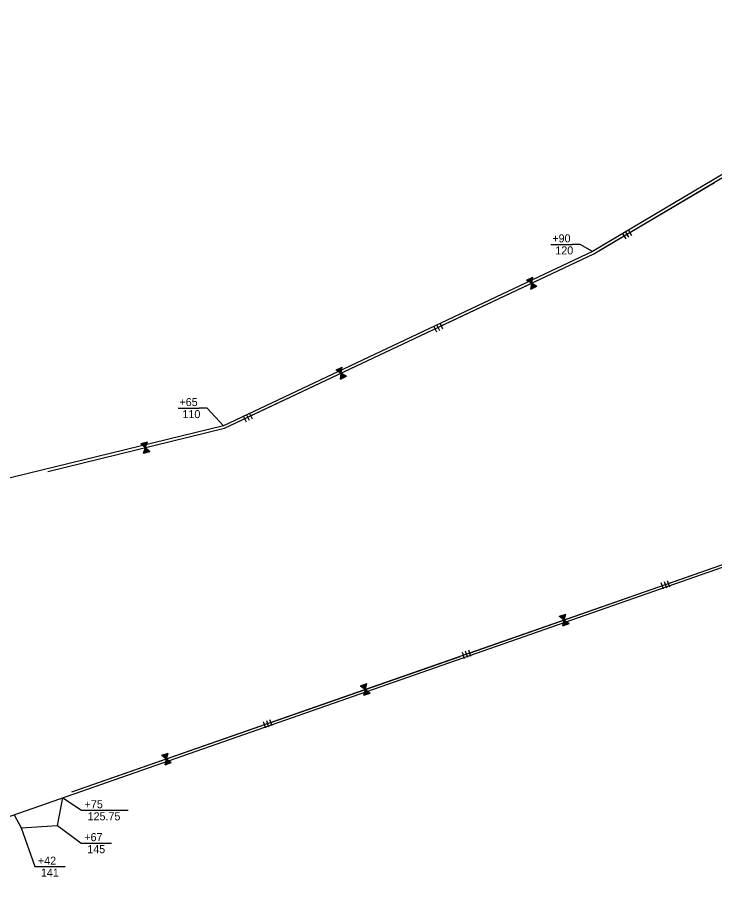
# Model space of a CAD drawing. Extents: x 979729 to 993523, y 1834148 to 1845433.
# Drawn here: x 990066 to 990587, y 1838700 to 1839360 of the extents above; entities that cross this region are included whole.
import ezdxf

# ---------------------------------------------------------------- set-up
doc = ezdxf.new("R2010")
doc.units = 0
for name, color, linetype in [('42', 7, 'Continuous'), ('51', 7, 'Continuous'), ('53', 7, 'Continuous'), ('R_Draft', 7, 'Continuous')]:
    doc.layers.add(name, color=color, linetype=linetype)

msp = doc.modelspace()

# ---------------------------------------------------------------- linework, layer by layer
at = {"layer": '42'}
for p, q in [((990496.48, 1839183.82), (990791.28, 1839358.59)), ((990522.05, 1839201.89), (990524.6, 1839197.59)), ((990517.75, 1839199.34), (990520.3, 1839195.04)), ((990519.9, 1839200.62), (990522.45, 1839196.32)), ((990220.2, 1839053.4), (990496.48, 1839183.82)), ((990446.24, 1839164.25), (990450.1, 1839161.93)), ((990446.31, 1839164.23), (990446.32, 1839164.29)), ((990446.55, 1839164.11), (990446.59, 1839164.42)), ((990446.78, 1839163.95), (990446.87, 1839164.55)), ((990447.01, 1839163.83), (990447.14, 1839164.68)), ((990447.24, 1839163.67), (990447.41, 1839164.81)), ((990447.47, 1839163.51), (990447.68, 1839164.94)), ((990447.71, 1839163.39), (990447.95, 1839165.06)), ((990447.95, 1839163.34), (990448.2, 1839165.03)), ((990448.17, 1839163.14), (990448.5, 1839165.32)), ((990448.41, 1839163.02), (990448.77, 1839165.45)), ((990448.63, 1839162.83), (990449.04, 1839165.58)), ((990448.87, 1839162.74), (990449.31, 1839165.7)), ((990449.1, 1839162.56), (990449.58, 1839165.83)), ((990449.33, 1839162.44), (990449.85, 1839165.96)), ((990449.56, 1839162.28), (990450.13, 1839166.09)), ((990449.8, 1839162.18), (990450.4, 1839166.22)), ((990450.03, 1839162), (990450.67, 1839166.35)), ((990450.1, 1839161.93), (990450.76, 1839166.39)), ((990449.44, 1839157.47), (990450.1, 1839161.93)), ((990449.47, 1839157.55), (990449.52, 1839157.51)), ((990449.53, 1839157.8), (990449.8, 1839157.64)), ((990449.55, 1839158.08), (990450.07, 1839157.77)), ((990449.61, 1839158.34), (990450.34, 1839157.9)), ((990449.63, 1839158.62), (990450.61, 1839158.02)), ((990449.65, 1839158.89), (990450.88, 1839158.15)), ((990449.71, 1839159.15), (990451.15, 1839158.28)), ((990449.81, 1839159.67), (990451.7, 1839158.54)), ((990449.82, 1839159.38), (990451.28, 1839158.5)), ((990449.87, 1839160.22), (990452.24, 1839158.79)), ((990449.87, 1839159.93), (990451.97, 1839158.67)), ((990449.95, 1839160.76), (990452.79, 1839159.05)), ((990449.95, 1839160.47), (990452.51, 1839158.92)), ((990450, 1839161.02), (990453.06, 1839159.18)), ((990450.03, 1839161.29), (990453.33, 1839159.31)), ((990450.1, 1839161.93), (990453.96, 1839159.61)), ((990450.1, 1839161.83), (990453.87, 1839159.56)), ((990450.11, 1839161.54), (990453.6, 1839159.44)), ((990376.69, 1839130.04), (990378.82, 1839125.52)), ((990378.95, 1839131.11), (990381.08, 1839126.59)), ((990381.21, 1839132.17), (990383.34, 1839127.65)), ((990303.81, 1839097.02), (990307.67, 1839094.69)), ((990303.89, 1839096.99), (990303.89, 1839097.06)), ((990304.12, 1839096.88), (990304.17, 1839097.19)), ((990304.35, 1839096.71), (990304.44, 1839097.31)), ((990304.59, 1839096.6), (990304.71, 1839097.44)), ((990304.81, 1839096.44), (990304.98, 1839097.57)), ((990305.04, 1839096.28), (990305.25, 1839097.7)), ((990305.28, 1839096.16), (990305.53, 1839097.83)), ((990305.52, 1839096.1), (990305.77, 1839097.79)), ((990305.75, 1839095.91), (990306.07, 1839098.08)), ((990305.98, 1839095.79), (990306.34, 1839098.21)), ((990306.21, 1839095.6), (990306.61, 1839098.34)), ((990306.45, 1839095.51), (990306.88, 1839098.47)), ((990306.67, 1839095.32), (990307.16, 1839098.6)), ((990306.9, 1839095.2), (990307.43, 1839098.73)), ((990307.13, 1839095.04), (990307.7, 1839098.85)), ((990307.37, 1839094.95), (990307.97, 1839098.98)), ((990307.6, 1839094.76), (990308.24, 1839099.11)), ((990307.67, 1839094.69), (990308.33, 1839099.15)), ((990307.01, 1839090.24), (990307.67, 1839094.69)), ((990307.04, 1839090.31), (990307.1, 1839090.28)), ((990307.1, 1839090.57), (990307.37, 1839090.4)), ((990307.12, 1839090.85), (990307.64, 1839090.53)), ((990307.18, 1839091.1), (990307.91, 1839090.66)), ((990307.2, 1839091.38), (990308.18, 1839090.79)), ((990307.22, 1839091.66), (990308.46, 1839090.92)), ((990307.28, 1839091.92), (990308.73, 1839091.05)), ((990307.38, 1839092.44), (990309.27, 1839091.3)), ((990307.39, 1839092.14), (990308.86, 1839091.26)), ((990307.44, 1839092.99), (990309.81, 1839091.56)), ((990307.44, 1839092.7), (990309.54, 1839091.43)), ((990307.52, 1839093.52), (990310.36, 1839091.82)), ((990307.52, 1839093.23), (990310.09, 1839091.69)), ((990307.58, 1839093.78), (990310.63, 1839091.94)), ((990307.6, 1839094.06), (990310.9, 1839092.07)), ((990307.67, 1839094.69), (990311.53, 1839092.37)), ((990307.68, 1839094.6), (990311.44, 1839092.33)), ((990307.68, 1839094.3), (990311.17, 1839092.2)), ((990236.52, 1839063.87), (990238.66, 1839059.35)), ((990238.78, 1839064.94), (990240.92, 1839060.42)), ((990234.26, 1839062.8), (990236.4, 1839058.28)), ((990088.31, 1839021.16), (990220.2, 1839053.4)), ((990157.85, 1839042.02), (990161.17, 1839038.97)), ((990157.92, 1839041.98), (990157.94, 1839042.04)), ((990158.12, 1839041.82), (990158.23, 1839042.11)), ((990158.31, 1839041.62), (990158.52, 1839042.19)), ((990158.52, 1839041.45), (990158.81, 1839042.26)), ((990158.71, 1839041.25), (990159.11, 1839042.33)), ((990158.91, 1839041.05), (990159.4, 1839042.4)), ((990159.11, 1839040.88), (990159.69, 1839042.47)), ((990159.34, 1839040.78), (990159.92, 1839042.39)), ((990159.52, 1839040.54), (990160.27, 1839042.61)), ((990159.63, 1839034.74), (990161.17, 1839038.97)), ((990159.73, 1839040.38), (990160.57, 1839042.69)), ((990159.91, 1839040.15), (990160.86, 1839042.76)), ((990160.13, 1839040.01), (990161.15, 1839042.83)), ((990160.31, 1839039.78), (990161.44, 1839042.9)), ((990160.52, 1839039.62), (990161.73, 1839042.97)), ((990160.54, 1839037.06), (990162.35, 1839035.4)), ((990160.6, 1839037.35), (990162.64, 1839035.47)), ((990160.71, 1839039.42), (990162.02, 1839043.04)), ((990160.73, 1839037.57), (990162.93, 1839035.54)), ((990160.78, 1839037.86), (990163.22, 1839035.61)), ((990160.89, 1839038.1), (990163.51, 1839035.69)), ((990160.92, 1839039.28), (990162.32, 1839043.11)), ((990160.97, 1839038.36), (990163.8, 1839035.76)), ((990161.09, 1839038.59), (990164.1, 1839035.83)), ((990161.11, 1839039.05), (990162.61, 1839043.18)), ((990161.15, 1839038.87), (990164.39, 1839035.9)), ((990161.17, 1839038.97), (990162.71, 1839043.21)), ((990161.17, 1839038.97), (990164.49, 1839035.92)), ((990159.67, 1839034.8), (990159.72, 1839034.76)), ((990159.78, 1839035.04), (990160.01, 1839034.83)), ((990159.86, 1839035.31), (990160.3, 1839034.9)), ((990159.96, 1839035.55), (990160.6, 1839034.97)), ((990160.04, 1839035.82), (990160.89, 1839035.04)), ((990160.12, 1839036.09), (990161.18, 1839035.11)), ((990160.23, 1839036.33), (990161.47, 1839035.19)), ((990160.38, 1839036.53), (990161.64, 1839035.37)), ((990160.43, 1839036.82), (990162.05, 1839035.33)), ((990106.16, 1838781.5), (990596.51, 1838952.77)), ((990546.69, 1838938.02), (990548.34, 1838933.3)), ((990549.05, 1838938.84), (990550.7, 1838934.12)), ((990551.41, 1838939.67), (990553.06, 1838934.95)), ((990470.75, 1838912.82), (990474.35, 1838910.1)), ((990470.82, 1838912.79), (990470.84, 1838912.85)), ((990471.04, 1838912.64), (990471.12, 1838912.95)), ((990471.25, 1838912.46), (990471.41, 1838913.05)), ((990471.48, 1838912.32), (990471.69, 1838913.15)), ((990471.69, 1838912.13), (990471.97, 1838913.25)), ((990471.9, 1838911.95), (990472.26, 1838913.35)), ((990472.12, 1838911.81), (990472.54, 1838913.44)), ((990472.36, 1838911.73), (990472.78, 1838913.38)), ((990472.56, 1838911.51), (990473.11, 1838913.64)), ((990472.78, 1838911.37), (990473.39, 1838913.74)), ((990472.98, 1838911.16), (990473.68, 1838913.84)), ((990473.21, 1838911.04), (990473.96, 1838913.94)), ((990473.42, 1838910.83), (990474.24, 1838914.04)), ((990473.64, 1838910.69), (990474.53, 1838914.14)), ((990473.85, 1838910.5), (990474.81, 1838914.24)), ((990474.08, 1838910.39), (990475.09, 1838914.34)), ((990474.28, 1838910.18), (990475.38, 1838914.43)), ((990474.35, 1838910.1), (990475.47, 1838914.47)), ((990473.22, 1838905.74), (990474.35, 1838910.1)), ((990473.26, 1838905.81), (990473.31, 1838905.77)), ((990473.34, 1838906.06), (990473.6, 1838905.87)), ((990473.39, 1838906.33), (990473.88, 1838905.97)), ((990473.48, 1838906.58), (990474.16, 1838906.07)), ((990473.53, 1838906.86), (990474.45, 1838906.17)), ((990473.58, 1838907.13), (990474.73, 1838906.26)), ((990473.67, 1838907.38), (990475.01, 1838906.36)), ((990473.8, 1838907.59), (990475.16, 1838906.56)), ((990473.82, 1838907.89), (990475.58, 1838906.56)), ((990473.91, 1838908.14), (990475.87, 1838906.66)), ((990473.94, 1838908.43), (990476.15, 1838906.76)), ((990474.04, 1838908.66), (990476.43, 1838906.86)), ((990474.07, 1838908.96), (990476.72, 1838906.96)), ((990474.15, 1838909.2), (990477, 1838907.06)), ((990474.21, 1838909.48), (990477.28, 1838907.16)), ((990474.31, 1838909.71), (990477.57, 1838907.26)), ((990474.34, 1838910), (990477.85, 1838907.35)), ((990474.35, 1838910.1), (990477.94, 1838907.39)), ((990398, 1838886.08), (990399.65, 1838881.36)), ((990400.36, 1838886.91), (990402.01, 1838882.19)), ((990402.72, 1838887.73), (990404.37, 1838883.01)), ((990322.06, 1838860.88), (990325.66, 1838858.17)), ((990322.13, 1838860.85), (990322.15, 1838860.91)), ((990322.35, 1838860.71), (990322.43, 1838861.01)), ((990322.56, 1838860.53), (990322.71, 1838861.11)), ((990322.79, 1838860.38), (990323, 1838861.21)), ((990323, 1838860.2), (990323.28, 1838861.31)), ((990323.21, 1838860.02), (990323.57, 1838861.41)), ((990323.43, 1838859.87), (990323.85, 1838861.51)), ((990323.67, 1838859.79), (990324.09, 1838861.45)), ((990323.87, 1838859.57), (990324.42, 1838861.71)), ((990324.09, 1838859.43), (990324.7, 1838861.81)), ((990324.29, 1838859.22), (990324.98, 1838861.91)), ((990324.52, 1838859.11), (990325.27, 1838862.01)), ((990324.73, 1838858.9), (990325.55, 1838862.1)), ((990324.95, 1838858.75), (990325.83, 1838862.2)), ((990325.16, 1838858.57), (990326.12, 1838862.3)), ((990325.39, 1838858.45), (990326.4, 1838862.4)), ((990325.59, 1838858.24), (990326.69, 1838862.5)), ((990325.66, 1838858.17), (990326.78, 1838862.53)), ((990324.53, 1838853.8), (990325.66, 1838858.17)), ((990324.57, 1838853.87), (990324.62, 1838853.83)), ((990324.65, 1838854.12), (990324.9, 1838853.93)), ((990324.7, 1838854.4), (990325.19, 1838854.03)), ((990324.79, 1838854.65), (990325.47, 1838854.13)), ((990324.84, 1838854.92), (990325.76, 1838854.23)), ((990324.89, 1838855.2), (990326.04, 1838854.33)), ((990324.97, 1838855.45), (990326.32, 1838854.43)), ((990325.11, 1838855.66), (990326.47, 1838854.63)), ((990325.13, 1838855.95), (990326.89, 1838854.63)), ((990325.22, 1838856.2), (990327.17, 1838854.73)), ((990325.24, 1838856.5), (990327.46, 1838854.83)), ((990325.35, 1838856.73), (990327.74, 1838854.92)), ((990325.38, 1838857.02), (990328.02, 1838855.02)), ((990325.46, 1838857.27), (990328.31, 1838855.12)), ((990325.52, 1838857.54), (990328.59, 1838855.22)), ((990325.62, 1838857.78), (990328.88, 1838855.32)), ((990325.65, 1838858.07), (990329.16, 1838855.42)), ((990325.66, 1838858.17), (990329.25, 1838855.45)), ((990249.31, 1838834.15), (990250.95, 1838829.43)), ((990251.67, 1838834.97), (990253.32, 1838830.25)), ((990254.03, 1838835.8), (990255.68, 1838831.08)), ((990173.37, 1838808.95), (990176.97, 1838806.23)), ((990173.44, 1838808.92), (990173.46, 1838808.98)), ((990173.66, 1838808.77), (990173.74, 1838809.08)), ((990173.87, 1838808.59), (990174.02, 1838809.18)), ((990174.09, 1838808.45), (990174.31, 1838809.28)), ((990174.3, 1838808.26), (990174.59, 1838809.38)), ((990174.52, 1838808.08), (990174.88, 1838809.48)), ((990174.74, 1838807.94), (990175.16, 1838809.57)), ((990174.97, 1838807.86), (990175.4, 1838809.51)), ((990175.18, 1838807.64), (990175.73, 1838809.77)), ((990175.4, 1838807.5), (990176.01, 1838809.87)), ((990175.6, 1838807.29), (990176.29, 1838809.97)), ((990175.83, 1838807.17), (990176.58, 1838810.07)), ((990175.84, 1838801.87), (990176.97, 1838806.23)), ((990176.03, 1838806.96), (990176.86, 1838810.17)), ((990176.25, 1838806.82), (990177.14, 1838810.27)), ((990176.47, 1838806.63), (990177.43, 1838810.37)), ((990176.69, 1838806.52), (990177.71, 1838810.47)), ((990176.9, 1838806.31), (990177.99, 1838810.57)), ((990176.96, 1838806.13), (990180.47, 1838803.48)), ((990176.97, 1838806.23), (990178.09, 1838810.6)), ((990176.97, 1838806.23), (990180.56, 1838803.52)), ((990175.88, 1838801.94), (990175.93, 1838801.9)), ((990175.96, 1838802.19), (990176.21, 1838802)), ((990176.01, 1838802.46), (990176.5, 1838802.1)), ((990176.1, 1838802.71), (990176.78, 1838802.2)), ((990176.15, 1838802.99), (990177.06, 1838802.3)), ((990176.2, 1838803.26), (990177.35, 1838802.4)), ((990176.28, 1838803.51), (990177.63, 1838802.49)), ((990176.42, 1838803.72), (990177.78, 1838802.69)), ((990176.44, 1838804.02), (990178.2, 1838802.69)), ((990176.53, 1838804.27), (990178.48, 1838802.79)), ((990176.55, 1838804.56), (990178.77, 1838802.89)), ((990176.66, 1838804.79), (990179.05, 1838802.99)), ((990176.69, 1838805.09), (990179.33, 1838803.09)), ((990176.77, 1838805.33), (990179.62, 1838803.19)), ((990176.82, 1838805.61), (990179.9, 1838803.29)), ((990176.93, 1838805.84), (990180.18, 1838803.39))]:
    msp.add_line(p, q, dxfattribs=at)
for points in [[(990523.33, 1839199.74), (990586.6, 1839237.25)], [(990382.28, 1839129.91), (990496.48, 1839183.82), (990516.88, 1839195.92)], [(990446.24, 1839164.25), (990450.76, 1839166.39)], [(990449.44, 1839157.47), (990453.96, 1839159.61)], [(990239.85, 1839062.68), (990375.49, 1839126.71)], [(990303.81, 1839097.02), (990308.33, 1839099.15)], [(990307.01, 1839090.24), (990311.53, 1839092.37)], [(990088.31, 1839021.16), (990220.2, 1839053.4), (990233.07, 1839059.48)], [(990157.85, 1839042.02), (990162.71, 1839043.21)], [(990159.63, 1839034.74), (990164.49, 1839035.92)], [(990552.23, 1838937.31), (990596.51, 1838952.77), (990675.14, 1839007.14)], [(990403.54, 1838885.37), (990545.15, 1838934.83)], [(990470.75, 1838912.82), (990475.47, 1838914.47)], [(990473.22, 1838905.74), (990477.94, 1838907.39)], [(990254.85, 1838833.44), (990396.46, 1838882.9)], [(990322.06, 1838860.88), (990326.78, 1838862.53)], [(990324.53, 1838853.8), (990329.25, 1838855.45)], [(990106.16, 1838781.5), (990247.77, 1838830.96)], [(990173.37, 1838808.95), (990178.09, 1838810.6)], [(990175.84, 1838801.87), (990180.56, 1838803.52)]]:
    msp.add_lwpolyline(points, dxfattribs=at)
at = {"layer": '51'}
for points in [[(990790.39, 1839360.39), (990495.54, 1839185.59), (990219.53, 1839055.3), (989873.17, 1838970.64), (989662.61, 1838927.17), (989537.01, 1838942.08), (989341.14, 1838901.64), (989234.92, 1838854.19)], [(990778.93, 1839076.47), (990597.42, 1838950.97), (990030.44, 1838752.94), (989776.33, 1838700.48)]]:
    msp.add_lwpolyline(points, dxfattribs=at)
at = {"layer": '53'}
for p, q in [((990095.4, 1838756.41), (990099.53, 1838777.07)), ((990062.99, 1838764.31), (990068.29, 1838754.63)), ((990068.29, 1838754.63), (990095.4, 1838756.41))]:
    msp.add_line(p, q, dxfattribs=at)
at = {"layer": 'R_Draft'}
for p, q in [((990464.38, 1839190.88), (990480.18, 1839190.88)), ((990185.56, 1839068.49), (990201.36, 1839068.49)), ((990119.34, 1838767.81), (990148.4, 1838767.81)), ((990119.11, 1838743.24), (990135.87, 1838743.24)), ((990084.44, 1838725.66), (990101.2, 1838725.66))]:
    msp.add_line(p, q, dxfattribs=at)
for points in [[(990495.54, 1839185.59), (990486.18, 1839190.88), (990480.18, 1839190.88)], [(990219.53, 1839055.3), (990207.36, 1839068.49), (990201.36, 1839068.49)], [(990099.53, 1838777.07), (990113.34, 1838767.81), (990119.34, 1838767.81)], [(990068.29, 1838754.63), (990078.44, 1838725.66), (990084.44, 1838725.66)], [(990095.4, 1838756.41), (990113.11, 1838743.24), (990119.11, 1838743.24)]]:
    msp.add_lwpolyline(points, dxfattribs=at)

# ---------------------------------------------------------------- texts
for s, p in [('+90', (990465.46, 1839192.38)), (' 120', (990465.46, 1839183.38)), ('+65', (990186.64, 1839069.99)), (' 110', (990186.64, 1839060.99)), ('+75', (990115.71, 1838769.31)), (' 125.75', (990115.71, 1838760.31)), ('+67', (990115.49, 1838744.74)), (' 145', (990115.49, 1838735.74)), ('+42', (990080.81, 1838727.16)), (' 141', (990080.81, 1838718.16))]:
    msp.add_text(s, height=6, rotation=360, dxfattribs=at).set_placement(p)

doc.saveas('drawing.dxf')
